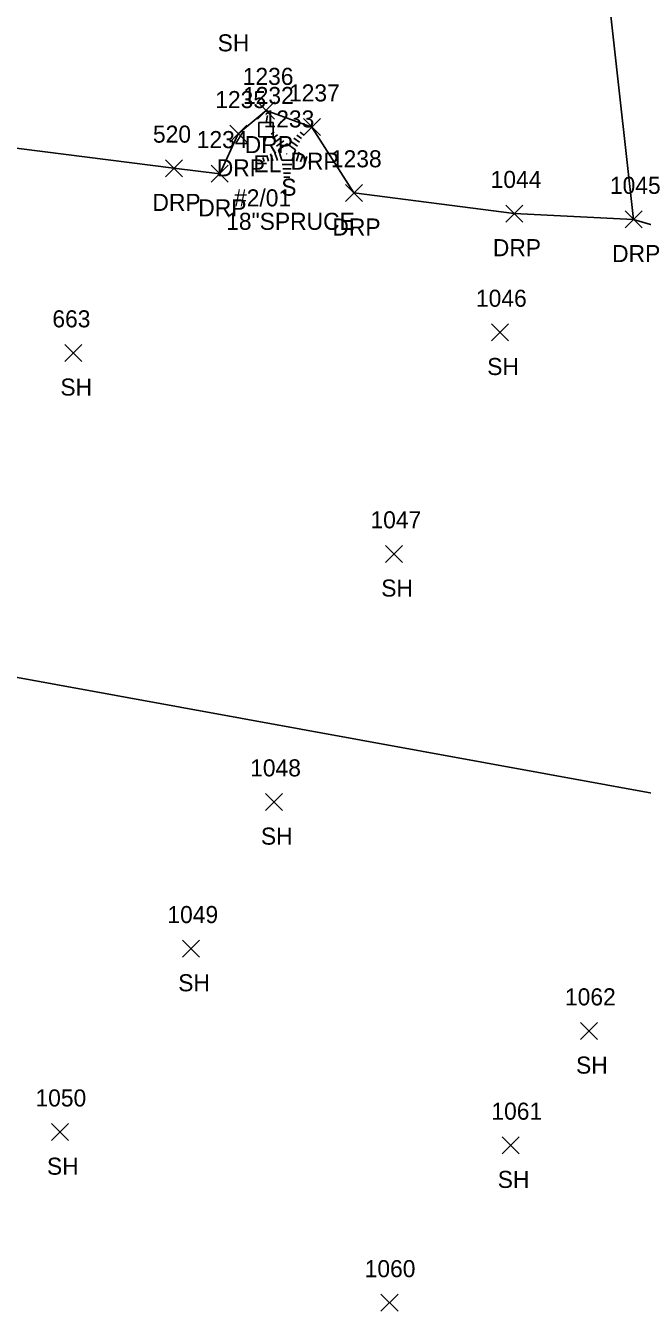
# Model space of a CAD drawing. Extents: x 1639430 to 1640195, y 612006 to 612917.
# Drawn here: x 1639907.9 to 1639980.2, y 612516.9 to 612667.5 of the extents above; entities that cross this region are included whole.
import ezdxf

# ---------------------------------------------------------------- set-up
doc = ezdxf.new("R2010")
doc.units = 0
for name, color, linetype in [('DCP', 7, 'Continuous'), ('L_A', 7, 'Continuous'), ('L_C', 7, 'Continuous'), ('L_I', 7, 'Continuous'), ('L_TIC', 7, 'Continuous'), ('LSOGP', 7, 'Continuous'), ('LTC', 7, 'Continuous'), ('R_A', 7, 'Continuous'), ('R_I', 7, 'Continuous'), ('R_TIC', 7, 'Continuous'), ('RDP', 7, 'Continuous'), ('U_A', 7, 'Continuous'), ('U_C', 7, 'Continuous'), ('U_I', 7, 'Continuous'), ('UEPT', 7, 'Continuous')]:
    doc.layers.add(name, color=color, linetype=linetype)

msp = doc.modelspace()

# ---------------------------------------------------------------- linework, layer by layer
at = {"layer": 'DCP'}
msp.add_lwpolyline([(1639875.64, 612596.85), (1640140.73, 612548.53)], dxfattribs=at)
at = {"layer": 'L_TIC'}
for points in [[(1639962.53, 612630.6), (1639964.53, 612632.6)], [(1639964.53, 612630.6), (1639962.53, 612632.6)], [(1639912.52, 612628.19), (1639914.52, 612630.19)], [(1639914.52, 612628.19), (1639912.52, 612630.19)], [(1639950.11, 612604.63), (1639952.11, 612606.63)], [(1639952.11, 612604.63), (1639950.11, 612606.63)], [(1639936.02, 612575.55), (1639938.02, 612577.55)], [(1639938.02, 612575.55), (1639936.02, 612577.55)], [(1639926.32, 612558.36), (1639928.32, 612560.36)], [(1639928.32, 612558.36), (1639926.32, 612560.36)], [(1639972.94, 612548.71), (1639974.94, 612550.71)], [(1639974.94, 612548.71), (1639972.94, 612550.71)], [(1639910.94, 612536.86), (1639912.94, 612538.86)], [(1639912.94, 612536.86), (1639910.94, 612538.86)], [(1639963.76, 612535.31), (1639965.76, 612537.31)], [(1639965.76, 612535.31), (1639963.76, 612537.31)], [(1639949.57, 612516.85), (1639951.57, 612518.85)], [(1639951.57, 612516.85), (1639949.57, 612518.85)]]:
    msp.add_lwpolyline(points, dxfattribs=at)
at = {"layer": 'LSOGP'}
msp.add_lwpolyline([(1639984.07, 612643.4), (1639979.17, 612644.84), (1639974.14, 612690.17), (1639965.85, 612711.74), (1639981.6, 612744.05)], dxfattribs=at)
at = {"layer": 'LTC'}
for p, q in [((1639936.7, 612654.83), (1639937.05, 612655.09)), ((1639940.1, 612655.07), (1639940.51, 612654.76)), ((1639936.91, 612654.36), (1639937.44, 612654.75)), ((1639937.12, 612653.9), (1639937.82, 612654.41)), ((1639937.33, 612653.43), (1639938.2, 612654.07)), ((1639937.55, 612652.98), (1639938.56, 612653.71)), ((1639938.56, 612653.71), (1639939.56, 612652.99)), ((1639938.98, 612654.02), (1639939.79, 612653.44)), ((1639939.35, 612654.37), (1639940.03, 612653.88)), ((1639939.72, 612654.72), (1639940.27, 612654.32)), ((1639935.73, 612652.11), (1639935.88, 612651.64)), ((1639936.18, 612652.32), (1639936.4, 612651.67)), ((1639936.64, 612652.54), (1639936.91, 612651.71)), ((1639937.1, 612652.76), (1639937.43, 612651.74)), ((1639937.55, 612652.98), (1639937.94, 612651.78)), ((1639939.56, 612652.99), (1639939.17, 612651.78)), ((1639940, 612652.72), (1639939.66, 612651.68)), ((1639940.44, 612652.47), (1639940.15, 612651.58)), ((1639940.89, 612652.22), (1639940.65, 612651.49)), ((1639939.17, 612651.78), (1639937.94, 612651.78)), ((1639939.13, 612651.28), (1639937.98, 612651.28)), ((1639939.05, 612650.78), (1639938.06, 612650.78)), ((1639941.33, 612651.96), (1639941.14, 612651.39)), ((1639938.96, 612650.28), (1639938.13, 612650.28)), ((1639938.88, 612649.78), (1639938.2, 612649.78))]:
    msp.add_line(p, q, dxfattribs=at)
at = {"layer": 'R_TIC'}
for points in [[(1639935.11, 612656.61), (1639937.11, 612658.61)], [(1639937.11, 612656.61), (1639935.11, 612658.61)], [(1639940.48, 612654.67), (1639942.48, 612656.67)], [(1639942.48, 612654.67), (1639940.48, 612656.67)], [(1639931.84, 612653.89), (1639933.84, 612655.89)], [(1639933.84, 612653.89), (1639931.84, 612655.89)], [(1639924.3, 612649.84), (1639926.3, 612651.84)], [(1639926.3, 612649.84), (1639924.3, 612651.84)], [(1639929.67, 612649.2), (1639931.67, 612651.2)], [(1639931.67, 612649.2), (1639929.67, 612651.2)], [(1639945.4, 612646.95), (1639947.4, 612648.95)], [(1639947.4, 612646.95), (1639945.4, 612648.95)], [(1639964.19, 612644.53), (1639966.19, 612646.53)], [(1639966.19, 612644.53), (1639964.19, 612646.53)], [(1639978.17, 612643.84), (1639980.17, 612645.84)], [(1639980.17, 612643.84), (1639978.17, 612645.84)]]:
    msp.add_lwpolyline(points, dxfattribs=at)
at = {"layer": 'RDP'}
for points in [[(1639925.3, 612650.84), (1639902.18, 612653.77), (1639898.8, 612654.77), (1639899.02, 612658.82), (1639898.69, 612662.04), (1639897.35, 612663.77), (1639891.72, 612666.05)], [(1639930.67, 612650.2), (1639932.84, 612654.89), (1639936.11, 612657.61), (1639941.48, 612655.67), (1639946.4, 612647.95)], [(1639925.3, 612650.84), (1639930.67, 612650.2)], [(1639946.4, 612647.95), (1639965.19, 612645.53)], [(1639965.19, 612645.53), (1639979.17, 612644.84), (1640018.38, 612633.31), (1640049.07, 612624.59), (1640074.87, 612616.7), (1640084.65, 612610.49), (1640094.93, 612602.25), (1640096.07, 612600.53), (1640095.84, 612598.58), (1640101.66, 612597.64), (1640108.13, 612607.66)]]:
    msp.add_lwpolyline(points, dxfattribs=at)
at = {"layer": 'UEPT'}
for p, q in [((1639936.26, 612657.03), (1639936.1, 612656.2)), ((1639935.26, 612654.53), (1639935.26, 612656.2)), ((1639935.26, 612656.2), (1639936.93, 612656.2)), ((1639936.1, 612655.37), (1639936.1, 612655.37)), ((1639936.93, 612656.2), (1639936.93, 612654.53)), ((1639936.93, 612654.53), (1639935.26, 612654.53)), ((1639935.85, 612653.7), (1639936.1, 612654.53))]:
    msp.add_line(p, q, dxfattribs=at)

# ---------------------------------------------------------------- texts
at = {"layer": 'L_A'}
for s, p in [('SH', (1639930.43, 612664.54)), ('S', (1639937.89, 612647.62)), ('SH', (1639962.02, 612626.6)), ('SH', (1639912, 612624.19)), ('SH', (1639949.6, 612600.63)), ('SH', (1639935.5, 612571.55)), ('SH', (1639925.81, 612554.36)), ('SH', (1639972.43, 612544.71)), ('SH', (1639910.43, 612532.86)), ('SH', (1639963.25, 612531.31))]:
    msp.add_text(s, height=2, dxfattribs=at).set_placement(p)
at = {"layer": 'L_C'}
msp.add_text('18"SPRUCE', height=2, dxfattribs=at).set_placement((1639931.43, 612643.62))
at = {"layer": 'L_I'}
for s, p in [('1233', (1639935.81, 612655.62)), ('1046', (1639960.7, 612634.6)), ('663', (1639911.06, 612632.19)), ('1047', (1639948.34, 612608.63)), ('1048', (1639934.24, 612579.55)), ('1049', (1639924.54, 612562.36)), ('1062', (1639971.13, 612552.71)), ('1050', (1639909.08, 612540.86)), ('1061', (1639962.51, 612539.31)), ('1060', (1639947.66, 612520.85))]:
    msp.add_text(s, height=2, dxfattribs=at).set_placement(p)
at = {"layer": 'LTC'}
msp.add_text('.', height=1.04, rotation=270, dxfattribs=at).set_placement((1639938.44, 612652.72))
at = {"layer": 'R_A'}
for p in [(1639933.6, 612652.61), (1639938.97, 612650.67), (1639930.33, 612649.89), (1639922.79, 612645.84), (1639928.16, 612645.2), (1639943.88, 612642.95), (1639962.68, 612640.53), (1639976.66, 612639.84)]:
    msp.add_text('DRP', height=2, dxfattribs=at).set_placement(p)
at = {"layer": 'R_I'}
for s, p in [('1236', (1639933.37, 612660.61)), ('1235', (1639930.15, 612657.89)), ('1237', (1639938.79, 612658.67)), ('520', (1639922.85, 612653.84)), ('1234', (1639927.98, 612653.2)), ('1238', (1639943.7, 612650.95)), ('1044', (1639962.42, 612648.53)), ('1045', (1639976.4, 612647.84))]:
    msp.add_text(s, height=2, dxfattribs=at).set_placement(p)
at = {"layer": 'U_A'}
msp.add_text('EL', height=2, dxfattribs=at).set_placement((1639934.63, 612650.37))
at = {"layer": 'U_C'}
msp.add_text('#2/01', height=2, dxfattribs=at).set_placement((1639932.35, 612646.37))
at = {"layer": 'U_I'}
msp.add_text('1232', height=2, dxfattribs=at).set_placement((1639933.4, 612658.37))

doc.saveas('drawing.dxf')
